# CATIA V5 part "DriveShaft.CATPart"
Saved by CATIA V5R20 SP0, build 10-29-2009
Part number: DriveShaft
Bounding box of the stored display mesh (mm): x -4.999 to 4.999, y -4.999 to 4.999, z 0 to 100
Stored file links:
  C:\Users\Robin\Desktop\Delar\DriveShaft.CATPart
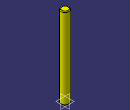
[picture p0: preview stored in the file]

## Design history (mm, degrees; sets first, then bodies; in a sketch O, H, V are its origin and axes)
Body1 (main body)
  DatumSurface1
  DatumCurve1
  DatumSurface2
  Sketch1 on face of DatumSurface1, origin (0, 0, 20), H (1, 0, 0), V (0, 1, 0)
    projected circle E1 centre (0, 0) radius 5 from edge of DatumCurve1
  Pad1: profile Sketch1, direction (0, 0, 1), length 80, opposite side up to face of DatumSurface2
  Fillet1: radius 1, on end face of Pad1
